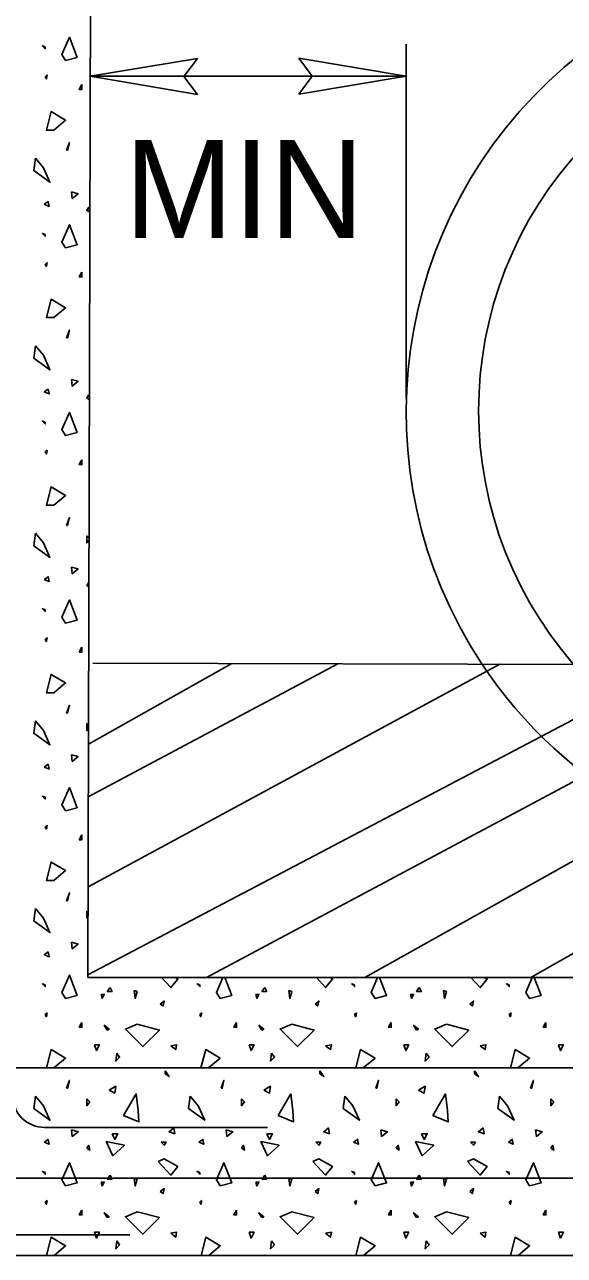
# Model space of a CAD drawing. Extents: x 9.6 to 16.8, y 2.2 to 12.2.
# Drawn here: x 14.996 to 15.328, y 6.99 to 7.746 of the extents above; entities that cross this region are included whole.
import ezdxf

# ---------------------------------------------------------------- set-up
doc = ezdxf.new("R2010")
doc.units = 0
for name, color, linetype in [('DETL-DIMS', 7, 'Continuous'), ('DETL-LINE', 7, 'Continuous'), ('DETL-NOTE', 7, 'Continuous'), ('DETL-PATT', 7, 'Continuous')]:
    doc.layers.add(name, color=color, linetype=linetype)

msp = doc.modelspace()

# ---------------------------------------------------------------- linework, layer by layer
at = {"layer": 'DETL-DIMS'}
for p, q in [((15.23039, 7.51631), (15.23039, 7.73388)), ((15.10224, 7.72498), (15.03631, 7.71412)), ((15.10224, 7.72498), (15.09396, 7.714)), ((15.16459, 7.72518), (15.23039, 7.71412)), ((15.16459, 7.72518), (15.17275, 7.7142)), ((15.23039, 7.71412), (15.03631, 7.71412)), ((15.10216, 7.70302), (15.03631, 7.71412)), ((15.10216, 7.70302), (15.09396, 7.714)), ((15.16451, 7.70322), (15.17275, 7.7142)), ((15.16451, 7.70322), (15.23039, 7.71412))]:
    msp.add_line(p, q, dxfattribs=at)
at = {"layer": 'DETL-LINE'}
for p, q in [((15.03902, 8.74647), (15.03486, 7.16059)), ((15.03792, 7.35373), (15.97557, 7.35125)), ((15.03486, 7.16059), (15.97506, 7.16059)), ((14.98871, 7.10522), (16.01604, 7.10522)), ((15.14525, 7.06859), (15.00827, 7.06859)), ((14.90416, 7.03737), (16.09322, 7.03737)), ((15.06071, 7.00267), (14.92373, 7.00267)), ((14.84702, 6.99), (16.1489, 6.99))]:
    msp.add_line(p, q, dxfattribs=at)
for centre, radius, start, end in [((15.51033, 7.50778), 0.27991, 325.61931, 213.35871), ((15.51198, 7.50873), 0.23705, 318.61489, 221.08317), ((15.51033, 7.50778), 0.27991, 213.35871, 325.61931), ((15.00829, 7.0882), 0.01961, 179.85139, 270)]:
    msp.add_arc(centre, radius, start, end, dxfattribs=at)
at = {"layer": 'DETL-PATT'}
for p, q in [((15.39698, 7.35278), (15.03486, 7.16235)), ((15.03502, 7.21631), (15.28796, 7.35306)), ((15.18839, 7.35333), (15.03514, 7.27153)), ((15.03525, 7.30396), (15.12337, 7.35349)), ((15.10784, 7.16059), (15.46718, 7.35259)), ((15.54729, 7.35239), (15.20498, 7.16059)), ((15.30702, 7.16059), (15.64373, 7.35212))]:
    msp.add_line(p, q, dxfattribs=at)
for points in [[(15.00871, 7.7322), (15.00698, 7.73275), (15.00871, 7.73106)], [(15.02125, 7.72384), (15.02831, 7.72569), (15.02353, 7.73812), (15.01886, 7.72753)], [(15.00996, 7.71498), (15.00871, 7.71384), (15.00941, 7.71255)], [(15.03129, 7.70902), (15.02957, 7.70608), (15.03129, 7.70608)], [(15.01404, 7.6811), (15.02125, 7.68714), (15.01235, 7.69239), (15.00941, 7.6811)], [(15.0218, 7.66867), (15.02239, 7.66867), (15.02353, 7.67345)], [(15.00275, 7.66384), (15.00165, 7.65624), (15.01165, 7.64902), (15.00757, 7.65792)], [(15.02478, 7.6431), (15.02533, 7.63902), (15.02886, 7.64196)], [(15.00812, 7.63549), (15.0111, 7.6342), (15.01051, 7.63718)], [(15.02125, 7.60867), (15.02831, 7.61051), (15.02353, 7.6229), (15.01886, 7.61231)], [(15.00871, 7.61698), (15.00698, 7.61757), (15.00871, 7.61584)], [(15.00996, 7.59976), (15.00871, 7.59863), (15.00941, 7.59737)], [(15.03129, 7.59384), (15.02957, 7.59086), (15.03129, 7.59086)], [(15.01404, 7.56588), (15.02125, 7.57196), (15.01235, 7.57718), (15.00941, 7.56588)], [(15.0218, 7.55345), (15.02239, 7.55345), (15.02353, 7.55827)], [(15.00275, 7.54867), (15.00165, 7.54102), (15.01165, 7.53384), (15.00757, 7.54275)], [(15.00812, 7.52027), (15.0111, 7.51902), (15.01051, 7.52196)], [(15.02478, 7.52792), (15.02533, 7.5238), (15.02886, 7.52678)], [(15.02125, 7.49345), (15.02831, 7.49529), (15.02353, 7.50773), (15.01886, 7.49714)], [(15.00871, 7.5018), (15.00698, 7.50235), (15.00871, 7.50067)], [(15.00996, 7.48455), (15.00871, 7.48345), (15.00941, 7.48216)], [(15.03129, 7.47863), (15.02957, 7.47569), (15.03129, 7.47569)], [(15.01404, 7.45067), (15.02125, 7.45675), (15.01235, 7.46196), (15.00941, 7.45067)], [(15.0218, 7.43827), (15.02239, 7.43827), (15.02353, 7.44306)], [(15.00275, 7.43345), (15.00165, 7.42584), (15.01165, 7.41863), (15.00757, 7.42753)], [(15.02478, 7.41271), (15.02533, 7.40863), (15.02886, 7.41157)], [(15.00812, 7.4051), (15.0111, 7.4038), (15.01051, 7.40678)], [(15.02125, 7.37827), (15.02831, 7.38008), (15.02353, 7.39251), (15.01886, 7.38192)], [(15.00871, 7.38659), (15.00698, 7.38714), (15.00871, 7.38545)], [(15.00996, 7.36937), (15.00871, 7.36824), (15.00941, 7.36698)], [(15.03129, 7.36345), (15.02957, 7.36047), (15.03129, 7.36047)], [(15.01404, 7.33549), (15.02125, 7.34157), (15.01235, 7.34678), (15.00941, 7.33549)], [(15.0218, 7.32306), (15.02239, 7.32306), (15.02353, 7.32784)], [(15.00275, 7.31827), (15.00165, 7.31063), (15.01165, 7.30345), (15.00757, 7.31231)], [(15.02478, 7.29749), (15.02533, 7.29341), (15.02886, 7.29639)], [(15.00812, 7.28988), (15.0111, 7.28863), (15.01051, 7.29157)], [(15.00871, 7.27137), (15.00698, 7.27196), (15.00871, 7.27027)], [(15.02125, 7.26306), (15.02831, 7.2649), (15.02353, 7.27733), (15.01886, 7.26675)], [(15.00996, 7.25416), (15.00871, 7.25302), (15.00941, 7.25176)], [(15.03129, 7.24824), (15.02957, 7.24525), (15.03129, 7.24525)], [(15.01404, 7.22027), (15.02125, 7.22635), (15.01235, 7.23157), (15.00941, 7.22027)], [(15.0218, 7.20784), (15.02239, 7.20784), (15.02353, 7.21267)], [(15.00275, 7.20306), (15.00165, 7.19545), (15.01165, 7.18824), (15.00757, 7.19714)], [(15.02478, 7.18231), (15.02533, 7.1782), (15.02886, 7.18118)], [(15.00812, 7.17467), (15.0111, 7.17341), (15.01051, 7.17639)], [(15.02125, 7.14784), (15.02831, 7.14969), (15.02353, 7.16212), (15.01886, 7.15153)], [(15.00871, 7.1562), (15.00698, 7.15675), (15.00871, 7.15506)], [(15.04851, 7.15451), (15.04976, 7.15208), (15.04682, 7.15208)], [(15.06333, 7.15267), (15.06404, 7.14784), (15.06518, 7.15208)], [(15.10369, 7.1562), (15.102, 7.15675), (15.10369, 7.15506)], [(15.14353, 7.15451), (15.14478, 7.15208), (15.1418, 7.15208)], [(15.15835, 7.15267), (15.15906, 7.14784), (15.16016, 7.15208)], [(15.19871, 7.1562), (15.19702, 7.15675), (15.19871, 7.15506)], [(15.23851, 7.15451), (15.2398, 7.15208), (15.23682, 7.15208)], [(15.25333, 7.15267), (15.25404, 7.14784), (15.25518, 7.15208)], [(15.29373, 7.1562), (15.29204, 7.15675), (15.29373, 7.15506)], [(15.04314, 7.15027), (15.04369, 7.14784), (15.04498, 7.15027)], [(15.07941, 7.14431), (15.0811, 7.14322), (15.0818, 7.14616)], [(15.13816, 7.15027), (15.13871, 7.14784), (15.14, 7.15027)], [(15.17443, 7.14431), (15.17612, 7.14322), (15.17682, 7.14616)], [(15.23318, 7.15027), (15.23373, 7.14784), (15.23498, 7.15027)], [(15.26945, 7.14431), (15.27114, 7.14322), (15.27184, 7.14616)], [(15.00996, 7.13898), (15.00871, 7.13784), (15.00941, 7.13655)], [(15.10498, 7.13898), (15.10369, 7.13784), (15.10439, 7.13655)], [(15.2, 7.13898), (15.19871, 7.13784), (15.19941, 7.13655)], [(15.29498, 7.13898), (15.29373, 7.13784), (15.29443, 7.13655)], [(15.03129, 7.13302), (15.02957, 7.13008), (15.03129, 7.13008)], [(15.04682, 7.12839), (15.04792, 7.12894), (15.04498, 7.13133)], [(15.06518, 7.13192), (15.07886, 7.12839), (15.06871, 7.1182), (15.05796, 7.12894)], [(15.12627, 7.13302), (15.12459, 7.13008), (15.12627, 7.13008)], [(15.1418, 7.12839), (15.14294, 7.12894), (15.14, 7.13133)], [(15.16016, 7.13192), (15.17388, 7.12839), (15.16369, 7.1182), (15.15298, 7.12894)], [(15.22129, 7.13302), (15.21961, 7.13008), (15.22129, 7.13008)], [(15.23682, 7.12839), (15.23796, 7.12894), (15.23498, 7.13133)], [(15.25518, 7.13192), (15.26886, 7.12839), (15.25871, 7.1182), (15.248, 7.12894)], [(15.31631, 7.13302), (15.31463, 7.13008), (15.31631, 7.13008)], [(15.01404, 7.1051), (15.02125, 7.11114), (15.01235, 7.11639), (15.00941, 7.1051)], [(15.03906, 7.11933), (15.04016, 7.1158), (15.042, 7.11933)], [(15.05275, 7.11412), (15.05204, 7.10933), (15.05443, 7.11173)], [(15.08592, 7.11878), (15.08886, 7.11639), (15.08945, 7.11933)], [(15.10906, 7.1051), (15.11627, 7.11114), (15.10737, 7.11639), (15.10439, 7.1051)], [(15.13404, 7.11933), (15.13518, 7.1158), (15.13702, 7.11933)], [(15.14776, 7.11412), (15.14706, 7.10933), (15.14945, 7.11173)], [(15.18094, 7.11878), (15.18388, 7.11639), (15.18447, 7.11933)], [(15.20408, 7.1051), (15.21129, 7.11114), (15.20239, 7.11639), (15.19941, 7.1051)], [(15.22906, 7.11933), (15.2302, 7.1158), (15.23204, 7.11933)], [(15.24275, 7.11412), (15.24204, 7.10933), (15.24447, 7.11173)], [(15.27592, 7.11878), (15.2789, 7.11639), (15.27945, 7.11933)], [(15.2991, 7.1051), (15.30627, 7.11114), (15.29741, 7.11639), (15.29443, 7.1051)], [(15.32408, 7.11933), (15.32522, 7.1158), (15.32706, 7.11933)], [(15.0218, 7.09267), (15.02239, 7.09267), (15.02353, 7.09745)], [(15.08239, 7.10337), (15.08239, 7.10157), (15.08478, 7.09984)], [(15.11682, 7.09267), (15.11741, 7.09267), (15.11851, 7.09745)], [(15.17741, 7.10337), (15.17741, 7.10157), (15.1798, 7.09984)], [(15.21184, 7.09267), (15.21239, 7.09267), (15.21353, 7.09745)], [(15.27239, 7.10337), (15.27239, 7.10157), (15.27482, 7.09984)], [(15.30686, 7.09267), (15.30741, 7.09267), (15.30855, 7.09745)], [(15.04792, 7.09153), (15.05145, 7.08969), (15.05204, 7.09392)], [(15.14294, 7.09153), (15.14647, 7.08969), (15.14706, 7.09392)], [(15.23796, 7.09153), (15.24149, 7.08969), (15.24204, 7.09392)], [(15.00275, 7.08784), (15.00165, 7.08024), (15.01165, 7.07302), (15.00757, 7.08192)], [(15.03424, 7.08616), (15.03424, 7.08192), (15.03608, 7.08431)], [(15.06573, 7.07898), (15.06627, 7.07192), (15.05682, 7.076), (15.06459, 7.08914)], [(15.09776, 7.08784), (15.09663, 7.08024), (15.10667, 7.07302), (15.10259, 7.08192)], [(15.12925, 7.08616), (15.12925, 7.08192), (15.1311, 7.08431)], [(15.16075, 7.07898), (15.16129, 7.07192), (15.15184, 7.076), (15.15961, 7.08914)], [(15.19278, 7.08784), (15.19165, 7.08024), (15.20169, 7.07302), (15.19757, 7.08192)], [(15.22427, 7.08616), (15.22427, 7.08192), (15.22612, 7.08431)], [(15.25576, 7.07898), (15.25631, 7.07192), (15.24686, 7.076), (15.25463, 7.08914)], [(15.2878, 7.08784), (15.28667, 7.08024), (15.29671, 7.07302), (15.29259, 7.08192)], [(15.31929, 7.08616), (15.31929, 7.08192), (15.3211, 7.08431)], [(15.08776, 7.06839), (15.08478, 7.06596), (15.08831, 7.06471)], [(15.18275, 7.06839), (15.1798, 7.06596), (15.18333, 7.06471)], [(15.27776, 7.06839), (15.27482, 7.06596), (15.27835, 7.06471)], [(15.00812, 7.05949), (15.0111, 7.0582), (15.01051, 7.06118)], [(15.02478, 7.0671), (15.02533, 7.06302), (15.02886, 7.06596)], [(15.04612, 7.06004), (15.05035, 7.05114), (15.05741, 7.05765)], [(15.04976, 7.06471), (15.05145, 7.06118), (15.05329, 7.06471)], [(15.10314, 7.05949), (15.10612, 7.0582), (15.10553, 7.06118)], [(15.1198, 7.0671), (15.12035, 7.06302), (15.12388, 7.06596)], [(15.1411, 7.06004), (15.14533, 7.05114), (15.15239, 7.05765)], [(15.14478, 7.06471), (15.14647, 7.06118), (15.14831, 7.06471)], [(15.19816, 7.05949), (15.2011, 7.0582), (15.20055, 7.06118)], [(15.21482, 7.0671), (15.21537, 7.06302), (15.2189, 7.06596)], [(15.23612, 7.06004), (15.24035, 7.05114), (15.24741, 7.05765)], [(15.2398, 7.06471), (15.24149, 7.06118), (15.24333, 7.06471)], [(15.29318, 7.05949), (15.29612, 7.0582), (15.29557, 7.06118)], [(15.3098, 7.0671), (15.31039, 7.06302), (15.31392, 7.06596)], [(15.03424, 7.0558), (15.03608, 7.05467), (15.03553, 7.05765)], [(15.08, 7.05949), (15.0818, 7.05765), (15.08294, 7.05949)], [(15.12925, 7.0558), (15.1311, 7.05467), (15.13051, 7.05765)], [(15.17498, 7.05949), (15.17682, 7.05765), (15.17796, 7.05949)], [(15.22427, 7.0558), (15.22612, 7.05467), (15.22553, 7.05765)], [(15.27, 7.05949), (15.27184, 7.05765), (15.27298, 7.05949)], [(15.31929, 7.0558), (15.3211, 7.05467), (15.32055, 7.05765)], [(15.02125, 7.03267), (15.02831, 7.03451), (15.02353, 7.0469), (15.01886, 7.03631)], [(15.07816, 7.04761), (15.08592, 7.03929), (15.09016, 7.04451), (15.0818, 7.04933)], [(15.11627, 7.03267), (15.12333, 7.03451), (15.11851, 7.0469), (15.11388, 7.03631)], [(15.17318, 7.04761), (15.18094, 7.03929), (15.18518, 7.04451), (15.17682, 7.04933)], [(15.21129, 7.03267), (15.21835, 7.03451), (15.21353, 7.0469), (15.20886, 7.03631)], [(15.26816, 7.04761), (15.27592, 7.03929), (15.28016, 7.04451), (15.27184, 7.04933)], [(15.30627, 7.03267), (15.31333, 7.03451), (15.30855, 7.0469), (15.30388, 7.03631)], [(15.00871, 7.04098), (15.00698, 7.04157), (15.00871, 7.03984)], [(15.04851, 7.03929), (15.04976, 7.0369), (15.04682, 7.0369)], [(15.06333, 7.03745), (15.06404, 7.03267), (15.06518, 7.0369)], [(15.10369, 7.04098), (15.102, 7.04157), (15.10369, 7.03984)], [(15.14353, 7.03929), (15.14478, 7.0369), (15.1418, 7.0369)], [(15.15835, 7.03745), (15.15906, 7.03267), (15.16016, 7.0369)], [(15.19871, 7.04098), (15.19702, 7.04157), (15.19871, 7.03984)], [(15.23851, 7.03929), (15.2398, 7.0369), (15.23682, 7.0369)], [(15.25333, 7.03745), (15.25404, 7.03267), (15.25518, 7.0369)], [(15.29373, 7.04098), (15.29204, 7.04157), (15.29373, 7.03984)], [(15.04314, 7.03506), (15.04369, 7.03267), (15.04498, 7.03506)], [(15.07941, 7.02914), (15.0811, 7.028), (15.0818, 7.03098)], [(15.13816, 7.03506), (15.13871, 7.03267), (15.14, 7.03506)], [(15.17443, 7.02914), (15.17612, 7.028), (15.17682, 7.03098)], [(15.23318, 7.03506), (15.23373, 7.03267), (15.23498, 7.03506)], [(15.26945, 7.02914), (15.27114, 7.028), (15.27184, 7.03098)], [(15.00996, 7.02376), (15.00871, 7.02263), (15.00941, 7.02137)], [(15.10498, 7.02376), (15.10369, 7.02263), (15.10439, 7.02137)], [(15.2, 7.02376), (15.19871, 7.02263), (15.19941, 7.02137)], [(15.29498, 7.02376), (15.29373, 7.02263), (15.29443, 7.02137)], [(15.03129, 7.01784), (15.02957, 7.01486), (15.03129, 7.01486)], [(15.04682, 7.01318), (15.04792, 7.01373), (15.04498, 7.01616)], [(15.06518, 7.01671), (15.07886, 7.01318), (15.06871, 7.00302), (15.05796, 7.01373)], [(15.12627, 7.01784), (15.12459, 7.01486), (15.12627, 7.01486)], [(15.1418, 7.01318), (15.14294, 7.01373), (15.14, 7.01616)], [(15.16016, 7.01671), (15.17388, 7.01318), (15.16369, 7.00302), (15.15298, 7.01373)], [(15.22129, 7.01784), (15.21961, 7.01486), (15.22129, 7.01486)], [(15.23682, 7.01318), (15.23796, 7.01373), (15.23498, 7.01616)], [(15.25518, 7.01671), (15.26886, 7.01318), (15.25871, 7.00302), (15.248, 7.01373)], [(15.31631, 7.01784), (15.31463, 7.01486), (15.31631, 7.01486)], [(15.03906, 7.00416), (15.04016, 7.00063), (15.042, 7.00416)], [(15.08592, 7.00357), (15.08886, 7.00118), (15.08945, 7.00416)], [(15.13404, 7.00416), (15.13518, 7.00063), (15.13702, 7.00416)], [(15.18094, 7.00357), (15.18388, 7.00118), (15.18447, 7.00416)], [(15.22906, 7.00416), (15.2302, 7.00063), (15.23204, 7.00416)], [(15.27592, 7.00357), (15.2789, 7.00118), (15.27945, 7.00416)], [(15.32408, 7.00416), (15.32522, 7.00063), (15.32706, 7.00416)], [(15.05275, 6.9989), (15.05204, 6.99412), (15.05443, 6.99651)], [(15.14776, 6.9989), (15.14706, 6.99412), (15.14945, 6.99651)], [(15.24275, 6.9989), (15.24204, 6.99412), (15.24447, 6.99651)]]:
    msp.add_lwpolyline(points, close=True, dxfattribs=at)
for points in [[(15.0358, 7.63212), (15.03553, 7.63365), (15.03424, 7.6318), (15.0358, 7.63082)], [(15.03557, 7.51812), (15.03553, 7.51843), (15.03424, 7.51663), (15.03557, 7.5158)], [(15.03541, 7.43059), (15.03424, 7.43176), (15.03424, 7.42753), (15.03541, 7.42906)], [(15.03533, 7.40302), (15.03424, 7.40141), (15.03533, 7.40071)], [(15.03518, 7.31565), (15.03424, 7.31655), (15.03424, 7.31231), (15.03518, 7.31353)], [(15.03494, 7.20067), (15.03424, 7.20137), (15.03424, 7.19714), (15.03494, 7.19804)], [(15.08024, 7.16059), (15.08592, 7.15451), (15.09016, 7.15973), (15.08867, 7.16059)], [(15.11784, 7.16059), (15.11388, 7.15153), (15.11627, 7.14784), (15.12333, 7.14969), (15.1191, 7.16059)], [(15.17525, 7.16059), (15.18094, 7.15451), (15.18518, 7.15973), (15.18369, 7.16059)], [(15.21286, 7.16059), (15.20886, 7.15153), (15.21129, 7.14784), (15.21835, 7.14969), (15.21412, 7.16059)], [(15.27024, 7.16059), (15.27592, 7.15451), (15.28016, 7.15973), (15.27867, 7.16059)], [(15.30788, 7.16059), (15.30388, 7.15153), (15.30627, 7.14784), (15.31333, 7.14969), (15.30914, 7.16059)], [(15.0142, 6.99), (15.02125, 6.99596), (15.01235, 7.00118), (15.00945, 6.99)], [(15.10922, 6.99), (15.11627, 6.99596), (15.10737, 7.00118), (15.10443, 6.99)], [(15.20424, 6.99), (15.21129, 6.99596), (15.20239, 7.00118), (15.19945, 6.99)], [(15.29925, 6.99), (15.30627, 6.99596), (15.29741, 7.00118), (15.29447, 6.99)]]:
    msp.add_lwpolyline(points, dxfattribs=at)

# ---------------------------------------------------------------- texts
at = {"layer": 'DETL-NOTE'}
msp.add_text('MIN', height=0.06, dxfattribs=at).set_placement((15.05741, 7.6149))

doc.saveas('drawing.dxf')
